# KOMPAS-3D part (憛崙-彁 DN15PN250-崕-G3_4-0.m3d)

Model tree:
1. Объединить компоненты:1  (labels: СЕНС-ПР DN15PN250-НО-G3/4-0)

Referenced files in D:\Савин\!СЕНСОР\3D для заказчика\!Новый перечень\СЕНС-ПР\6. СЕНС-ПР-PN250-НО\DN15\: СЕНС-ПР DN15PN250-НО-G3_4-0.a3d
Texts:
  СЕНС-ПР DN15PN250-НО-G3/4-0
  ООО НПП Сенсор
